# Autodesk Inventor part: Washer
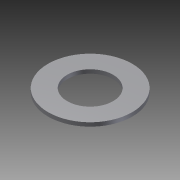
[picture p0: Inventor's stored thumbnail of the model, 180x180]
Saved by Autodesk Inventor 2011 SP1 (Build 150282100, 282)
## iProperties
Created: 2011-10
Part Number: Washer
Document SubType Name: Modeling
Designer: sdarley
Density: 1 g/cm^3
Author: sdarley
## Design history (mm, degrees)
sketch "Sketch1"
  geometry: C1 r 3 at (0, 0); C2 r 5.5 at (0, 0); 1 further point
  constraints: 2 centre point, 2 coincident
  dimensions: "d0" = 6 diameter of C1; "d1" = 11 diameter of C2
extrude "Extrusion1" new body sketch "Sketch1" distance "d2" = 0.5; taper "d3" = 0 deg
body "Solid1"
